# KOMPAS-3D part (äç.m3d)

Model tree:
1. Эскиз:1
2. Операция выдавливания:1
     Расстояние 1 = 0.8; Расстояние 2 = 1.1
3. Эскиз:2
4. Операция выдавливания:2
     Расстояние 1 = 0.8; Расстояние 2 = 1.1
5. Скругление:1
     Радиус = 0.4
6. Эскиз:3
7. Операция выдавливания:3
     Расстояние 1 = 0.5; Расстояние 2 = 1.1

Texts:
  Сплав АЛ8  ГОСТ 1583-93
